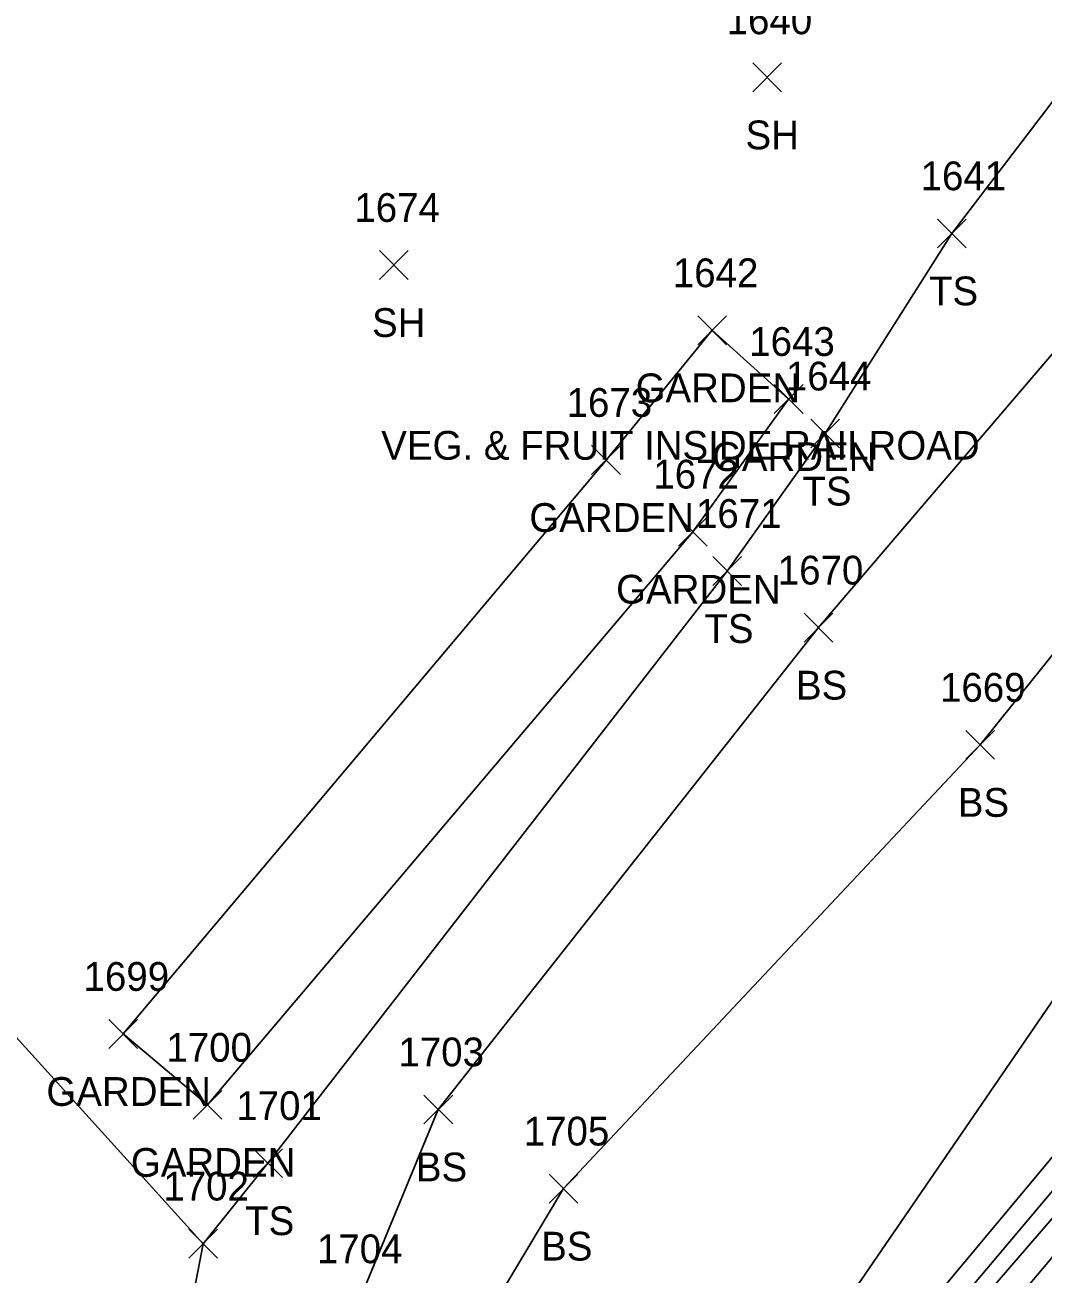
# Model space of a CAD drawing. Extents: x 1520648 to 1523413, y 732854 to 735518.
# Drawn here: x 1522197 to 1522267.9, y 734021.8 to 734108.7 of the extents above; entities that cross this region are included whole.
import ezdxf

# ---------------------------------------------------------------- set-up
doc = ezdxf.new("R2010")
doc.units = 0
for name, color, linetype in [('L_A', 7, 'Continuous'), ('L_C', 7, 'Continuous'), ('L_I', 7, 'Continuous'), ('L_TIC', 7, 'Continuous'), ('LAPB', 7, 'Continuous'), ('LAWE', 7, 'Continuous'), ('LELB', 7, 'Continuous')]:
    doc.layers.add(name, color=color, linetype=linetype)

msp = doc.modelspace()

# ---------------------------------------------------------------- linework, layer by layer
at = {"layer": 'L_TIC'}
for points in [[(1522247.64, 734104.101), (1522249.64, 734106.101)], [(1522249.64, 734104.101), (1522247.64, 734106.101)], [(1522260.477, 734093.253), (1522262.477, 734095.253)], [(1522262.477, 734093.253), (1522260.477, 734095.253)], [(1522221.674, 734091.052), (1522223.674, 734093.052)], [(1522223.674, 734091.052), (1522221.674, 734093.052)], [(1522243.815, 734086.513), (1522245.815, 734088.513)], [(1522245.815, 734086.513), (1522243.815, 734088.513)], [(1522243.815, 734086.513), (1522245.815, 734088.513)], [(1522245.815, 734086.513), (1522243.815, 734088.513)], [(1522249.127, 734081.734), (1522251.127, 734083.734)], [(1522251.127, 734081.734), (1522249.127, 734083.734)], [(1522251.674, 734079.33), (1522253.674, 734081.33)], [(1522253.674, 734079.33), (1522251.674, 734081.33)], [(1522236.429, 734077.494), (1522238.429, 734079.494)], [(1522238.429, 734077.494), (1522236.429, 734079.494)], [(1522242.462, 734072.51), (1522244.462, 734074.51)], [(1522244.462, 734072.51), (1522242.462, 734074.51)], [(1522244.86, 734069.774), (1522246.86, 734071.774)], [(1522246.86, 734069.774), (1522244.86, 734071.774)], [(1522251.197, 734065.837), (1522253.197, 734067.837)], [(1522253.197, 734065.837), (1522251.197, 734067.837)], [(1522262.448, 734057.684), (1522264.448, 734059.684)], [(1522264.448, 734057.684), (1522262.448, 734059.684)], [(1522202.85, 734037.583), (1522204.85, 734039.583)], [(1522204.85, 734037.583), (1522202.85, 734039.583)], [(1522208.722, 734032.652), (1522210.722, 734034.652)], [(1522210.722, 734032.652), (1522208.722, 734034.652)], [(1522208.722, 734032.652), (1522210.722, 734034.652)], [(1522210.722, 734032.652), (1522208.722, 734034.652)], [(1522224.769, 734032.335), (1522226.769, 734034.335)], [(1522226.769, 734032.335), (1522224.769, 734034.335)], [(1522212.927, 734028.597), (1522214.927, 734030.597)], [(1522214.927, 734028.597), (1522212.927, 734030.597)], [(1522233.48, 734026.828), (1522235.48, 734028.828)], [(1522235.48, 734026.828), (1522233.48, 734028.828)], [(1522208.424, 734023.002), (1522210.424, 734025.002)], [(1522210.424, 734023.002), (1522208.424, 734025.002)], [(1522208.424, 734023.002), (1522210.424, 734025.002)], [(1522210.424, 734023.002), (1522208.424, 734025.002)]]:
    msp.add_lwpolyline(points, dxfattribs=at)
at = {"layer": 'LAPB'}
for points in [[(1522244.815, 734087.513), (1522237.429, 734078.494), (1522203.85, 734038.583), (1522209.722, 734033.652)], [(1522244.815, 734087.513), (1522250.127, 734082.734), (1522243.462, 734073.51), (1522209.722, 734033.652)]]:
    msp.add_lwpolyline(points, dxfattribs=at)
at = {"layer": 'LAWE'}
msp.add_lwpolyline([(1522250.491, 734235.037), (1522272.418, 734218.931), (1522297.866, 734198.743), (1522307.579, 734174.196), (1522311.425, 734163.768), (1522313.948, 734156.23), (1522320.922, 734149.602), (1522331.746, 734145.275), (1522341.38, 734144.282), (1522344.648, 734145.296), (1522354.267, 734148.786), (1522359.626, 734149.415), (1522357.593, 734144.359), (1522350.282, 734130.695), (1522326.677, 734100.964), (1522300.85, 734070.206), (1522283.214, 734045.187), (1522247.826, 734003.159), (1522235.935, 733986.962), (1522232.503, 733982.111), (1522233.889, 733977.864), (1522237.924, 733975.081)], dxfattribs=at)
at = {"layer": 'LELB'}
for points in [[(1522251.119, 734236.06), (1522272.787, 734219.747), (1522299.135, 734200.043), (1522308.726, 734174.595), (1522312.876, 734163.824), (1522314.782, 734156.547), (1522320.994, 734151.619), (1522332.232, 734147.487), (1522341.112, 734146.747), (1522344.976, 734145.996), (1522353.744, 734149.873), (1522359.959, 734152.11), (1522361.653, 734150.335), (1522359.006, 734144.156), (1522350.925, 734130.052), (1522328.139, 734100.37), (1522301.957, 734069.708), (1522284.253, 734044.067), (1522248.494, 734002.647), (1522236.848, 733986.418), (1522234.99, 733978.889), (1522237.802, 733975.956)], [(1522244.934, 734228.517), (1522263.317, 734209.373), (1522289.493, 734189.741), (1522306.793, 734166.34), (1522312.533, 734155.322), (1522317.625, 734143.646), (1522298.719, 734121.603), (1522271.826, 734089.823), (1522252.197, 734066.837), (1522225.769, 734033.335), (1522220.103, 734019.644), (1522210.973, 733988.138), (1522200.092, 733970.453)], [(1522237.384, 734218.531), (1522258.218, 734200.842), (1522283.252, 734181.689), (1522301.322, 734163.169), (1522304.675, 734146.805), (1522288.264, 734129.349), (1522261.477, 734094.253), (1522252.674, 734080.33), (1522245.86, 734070.774), (1522213.927, 734029.597), (1522209.424, 734024.002), (1522201.643, 733983.589), (1522200.092, 733970.453), (1522201.997, 733964.193)], [(1522344.648, 734145.296), (1522347.169, 734143.458), (1522354.527, 734146.442), (1522357.593, 734144.359), (1522349.216, 734132.387), (1522324.183, 734103.261), (1522298.736, 734071.29), (1522282.293, 734046.597), (1522246.807, 734004.076), (1522231.674, 733985.079), (1522222.698, 733979.344)], [(1522331.746, 734145.275), (1522330.826, 734143.251), (1522307.65, 734116.035), (1522282.293, 734082.141), (1522263.448, 734058.684), (1522234.48, 734027.828), (1522226.547, 734014.571), (1522216.683, 733985.084), (1522201.997, 733964.193)], [(1522353.246, 734140.577), (1522319.919, 734106.375), (1522293, 734074.596), (1522275.622, 734051.294), (1522244.544, 734005.967), (1522222.698, 733979.344), (1522201.997, 733964.193), (1522167.916, 733938.992), (1522145.374, 733925.913), (1522137.653, 733917.419), (1522137.34, 733905.336), (1522137.089, 733900.599)], [(1522352.202, 734128.759), (1522329.533, 734099.474), (1522304.126, 734068.773), (1522285.334, 734043.096), (1522250.233, 734001.404), (1522240.084, 733985.458), (1522239.336, 733981.939), (1522242.187, 733979.328), (1522245.314, 733977.405), (1522241.671, 733973.031), (1522239.463, 733974.659), (1522237.802, 733975.956)], [(1522137.777, 734106.278), (1522153.378, 734084.657), (1522174.637, 734065), (1522193.513, 734041.538), (1522209.424, 734024.002)]]:
    msp.add_lwpolyline(points, dxfattribs=at)

# ---------------------------------------------------------------- texts
at = {"layer": 'L_A'}
for s, p in [('SH', (1522247.129, 734100.101)), ('TS', (1522259.886, 734089.253)), ('SH', (1522221.162, 734087.052)), ('GARDEN', (1522239.485, 734082.513)), ('GARDEN', (1522239.485, 734082.513)), ('GARDEN', (1522244.796, 734077.734)), ('TS', (1522251.083, 734075.33)), ('GARDEN', (1522232.098, 734073.494)), ('GARDEN', (1522238.131, 734068.51)), ('TS', (1522244.27, 734065.774)), ('BS', (1522250.638, 734061.837)), ('BS', (1522261.889, 734053.684)), ('GARDEN', (1522198.519, 734033.583)), ('GARDEN', (1522204.391, 734028.652)), ('GARDEN', (1522204.391, 734028.652)), ('BS', (1522224.21, 734028.335)), ('TS', (1522212.337, 734024.597)), ('BS', (1522232.921, 734022.828))]:
    msp.add_text(s, height=2, dxfattribs=at).set_placement(p)
at = {"layer": 'L_C'}
msp.add_text('VEG. & FRUIT INSIDE RAILROAD', height=2, dxfattribs=at).set_placement((1522221.8, 734078.513))
msp.add_text('VEG. & FRUIT INSIDE RAILROAD', height=2, dxfattribs=at).set_placement((1522221.8, 734078.513))
at = {"layer": 'L_I'}
for s, p in [('1640', (1522245.814, 734108.101)), ('1641', (1522259.303, 734097.253)), ('1674', (1522219.934, 734095.052)), ('1642', (1522242.075, 734090.513)), ('1642', (1522242.075, 734090.513)), ('1643', (1522247.387, 734085.734)), ('1644', (1522249.934, 734083.33)), ('1673', (1522234.689, 734081.494)), ('1672', (1522240.722, 734076.51)), ('1671', (1522243.687, 734073.774)), ('1670', (1522249.371, 734069.837)), ('1669', (1522260.653, 734061.684)), ('1699', (1522201.102, 734041.583)), ('1700', (1522206.864, 734036.652)), ('1700', (1522206.864, 734036.652)), ('1703', (1522222.997, 734036.335)), ('1701', (1522211.723, 734032.597)), ('1705', (1522231.709, 734030.828)), ('1702', (1522206.652, 734027.002)), ('1702', (1522206.652, 734027.002)), ('1704', (1522217.331, 734022.644))]:
    msp.add_text(s, height=2, dxfattribs=at).set_placement(p)

doc.saveas('drawing.dxf')
